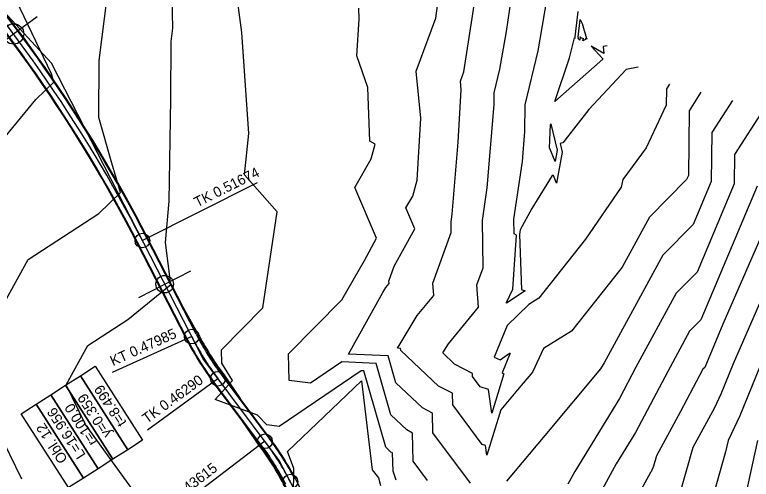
# Model space of a CAD drawing. Extents: x -549394 to -546608, y -1037055 to -1033629.
# Drawn here: x -548001.4 to -547749.6, y -1034578.2 to -1034419.6 of the extents above; entities that cross this region are included whole.
import ezdxf

# ---------------------------------------------------------------- set-up
doc = ezdxf.new("R2010")
doc.units = 0
for name, color, linetype in [('hlavni_vrst', 7, 'Continuous'), ('norm_vrst', 7, 'Continuous'), ('POLYGONY_SITUACE_PO', 7, 'Continuous'), ('u_sirka_1_0m', 7, 'Continuous'), ('u_sirka_1_5m', 7, 'Continuous'), ('x_navrh_C21', 7, 'Continuous'), ('x_osa_C21', 7, 'Continuous'), ('x_popis_oblouky_C21', 7, 'Continuous'), ('x_popis_pricne_rezy_C21', 7, 'Continuous'), ('x_popis_velky_C21', 7, 'Continuous')]:
    doc.layers.add(name, color=color, linetype=linetype)

msp = doc.modelspace()

# ---------------------------------------------------------------- linework, layer by layer
at = {"layer": 'hlavni_vrst'}
for p, q in [((-547972.53, -1034435.18), (-547967.9, -1034398.42)), ((-547847.85, -1034439), (-547844.03, -1034413.98)), ((-547808.1, -1034427.23), (-547808.09, -1034427.11)), ((-547808.1, -1034427.23), (-547808.1, -1034427.23)), ((-547808.09, -1034427.23), (-547808.1, -1034427.23)), ((-547808.09, -1034427.11), (-547808.03, -1034427.23)), ((-547808.03, -1034427.23), (-547808.09, -1034427.23)), ((-547972.63, -1034454.59), (-547972.53, -1034435.18)), ((-547849.06, -1034442.26), (-547847.85, -1034439)), ((-547848.77, -1034445.16), (-547849.06, -1034442.26)), ((-547849.84, -1034463.05), (-547848.77, -1034445.16)), ((-547766.85, -1034446.01), (-547770.88, -1034452.32)), ((-547770.88, -1034452.32), (-547771.13, -1034474.49)), ((-547968.22, -1034470.29), (-547972.63, -1034454.59)), ((-547851.85, -1034487.64), (-547849.84, -1034463.05)), ((-547965.24, -1034480.24), (-547968.22, -1034470.29)), ((-547771.13, -1034474.49), (-547771.77, -1034475.85)), ((-547771.77, -1034475.85), (-547784.47, -1034488.72)), ((-547972.63, -1034487.41), (-547965.24, -1034480.24)), ((-547996.78, -1034503.15), (-547972.63, -1034487.41)), ((-547852.24, -1034490.22), (-547851.85, -1034487.64)), ((-547784.47, -1034488.72), (-547793.79, -1034505.78)), ((-547852.18, -1034493.94), (-547852.24, -1034490.22)), ((-547858.43, -1034511.17), (-547852.18, -1034493.94)), ((-547737, -1034495.44), (-547755.79, -1034538.71)), ((-548017.39, -1034540.43), (-547996.78, -1034503.15)), ((-547793.79, -1034505.78), (-547811.09, -1034527.65)), ((-547858.15, -1034515.37), (-547858.43, -1034511.17)), ((-547863.82, -1034522.3), (-547858.15, -1034515.37)), ((-547869.69, -1034531.9), (-547863.82, -1034522.3)), ((-547811.09, -1034527.65), (-547820.62, -1034533.57)), ((-547870.56, -1034533.46), (-547869.69, -1034531.9)), ((-547869.55, -1034533.5), (-547870.56, -1034533.46)), ((-547869.36, -1034534.18), (-547869.55, -1034533.5)), ((-547856.51, -1034546.33), (-547869.36, -1034534.18)), ((-547820.62, -1034533.57), (-547824.44, -1034541.59)), ((-547755.79, -1034538.71), (-547760.02, -1034549.09)), ((-547998.99, -1034578.18), (-548017.39, -1034540.43)), ((-547824.44, -1034541.59), (-547829.52, -1034547.66)), ((-547851.77, -1034548.83), (-547856.51, -1034546.33)), ((-547829.52, -1034547.66), (-547835.23, -1034554.45)), ((-547851.69, -1034552.72), (-547851.77, -1034548.83)), ((-547760.02, -1034549.09), (-547762.25, -1034553.76)), ((-547841.58, -1034566.29), (-547851.69, -1034552.72)), ((-547835.23, -1034554.45), (-547839.96, -1034569.96)), ((-547762.25, -1034553.76), (-547769.61, -1034567.38)), ((-547840.42, -1034566.64), (-547841.58, -1034566.29)), ((-547839.96, -1034569.96), (-547840.42, -1034566.64)), ((-547769.61, -1034567.38), (-547774.62, -1034585.07))]:
    msp.add_line(p, q, dxfattribs=at)
at = {"layer": 'norm_vrst'}
for p, q in [((-547947.33, -1034424.17), (-547947.99, -1034390.61)), ((-547923.78, -1034425.62), (-547927.84, -1034394.89)), ((-547833.31, -1034425.23), (-547831.2, -1034411.45)), ((-547988.82, -1034439.7), (-548000.83, -1034414.53)), ((-547857.49, -1034420.69), (-547856.85, -1034416.52)), ((-547822.51, -1034431.85), (-547819.48, -1034414.43)), ((-547883.65, -1034421.09), (-547883.74, -1034417.3)), ((-547809.86, -1034427.06), (-547808.83, -1034418.48)), ((-547884.5, -1034433.57), (-547883.65, -1034421.09)), ((-547864.21, -1034438.77), (-547857.49, -1034420.69)), ((-547808.76, -1034427.19), (-547808.14, -1034421.14)), ((-547808.14, -1034421.14), (-547807.38, -1034422.59)), ((-547947.9, -1034428.68), (-547947.33, -1034424.17)), ((-547807.38, -1034422.59), (-547805.94, -1034427.64)), ((-547921.36, -1034460.11), (-547923.78, -1034425.62)), ((-547835.56, -1034438.13), (-547833.31, -1034425.23)), ((-547948, -1034448.39), (-547947.9, -1034428.68)), ((-547811.74, -1034434.26), (-547810.11, -1034427.46)), ((-547810.11, -1034427.46), (-547809.86, -1034427.5)), ((-547809.86, -1034427.5), (-547809.86, -1034427.06)), ((-547808.78, -1034427.51), (-547808.73, -1034427.2)), ((-547808.19, -1034428.24), (-547808.78, -1034427.51)), ((-547808.73, -1034427.2), (-547808.76, -1034427.19)), ((-547808.08, -1034427.33), (-547808.19, -1034428.24)), ((-547808.07, -1034427.33), (-547808.08, -1034427.33)), ((-547807.96, -1034427.34), (-547808.07, -1034427.33)), ((-547807.96, -1034427.34), (-547807.01, -1034427.61)), ((-547807.21, -1034428.43), (-547807, -1034427.63)), ((-547806.3, -1034427.96), (-547807.21, -1034428.43)), ((-547807.21, -1034428.43), (-547807.21, -1034428.43)), ((-547807.21, -1034428.43), (-547807.21, -1034428.43)), ((-547807.21, -1034428.43), (-547807.21, -1034428.43)), ((-547807.02, -1034427.63), (-547807.01, -1034427.61)), ((-547807, -1034427.63), (-547807.02, -1034427.63)), ((-547806.25, -1034427.66), (-547806.3, -1034427.96)), ((-547805.75, -1034427.74), (-547806.25, -1034427.66)), ((-547805.94, -1034427.64), (-547805.75, -1034427.74)), ((-547826.93, -1034450.37), (-547822.51, -1034431.85)), ((-547800.03, -1034432.81), (-547804.32, -1034430.28)), ((-547804.32, -1034430.28), (-547800.3, -1034434.75)), ((-547798.93, -1034430.17), (-547800.25, -1034430.4)), ((-547800.25, -1034430.4), (-547800.03, -1034432.81)), ((-547880.67, -1034444.43), (-547884.5, -1034433.57)), ((-547816.76, -1034449.19), (-547811.74, -1034434.26)), ((-547800.42, -1034434.72), (-547816.76, -1034449.19)), ((-547800.3, -1034434.75), (-547800.42, -1034434.72)), ((-547862.59, -1034454.86), (-547864.21, -1034438.77)), ((-547837.49, -1034446.25), (-547835.56, -1034438.13)), ((-547792.45, -1034438.21), (-547805.11, -1034451.9)), ((-547788.31, -1034437.48), (-547792.45, -1034438.21)), ((-547987.96, -1034442.56), (-547988.82, -1034439.7)), ((-547994.11, -1034448.52), (-547987.96, -1034442.56)), ((-547880.02, -1034462.74), (-547880.67, -1034444.43)), ((-547777.63, -1034443.25), (-547778.66, -1034444.85)), ((-547837.54, -1034450.22), (-547837.49, -1034446.25)), ((-547778.66, -1034444.85), (-547778.72, -1034450.47)), ((-548016.54, -1034475.52), (-547994.11, -1034448.52)), ((-547948.63, -1034483.2), (-547948, -1034448.39)), ((-547756.07, -1034448.78), (-547763.11, -1034459.78)), ((-547839.86, -1034478.64), (-547837.54, -1034450.22)), ((-547827.04, -1034459.45), (-547826.93, -1034450.37)), ((-547805.11, -1034451.9), (-547814.02, -1034463.33)), ((-547778.72, -1034450.47), (-547785.61, -1034465)), ((-547745.28, -1034451.54), (-547755.34, -1034467.25)), ((-547863.86, -1034475.99), (-547862.59, -1034454.86)), ((-547818.6, -1034465.16), (-547818.24, -1034457.04)), ((-547818.24, -1034457.04), (-547818.13, -1034456.86)), ((-547818.13, -1034456.86), (-547815.98, -1034465.84)), ((-547827.87, -1034469.65), (-547827.04, -1034459.45)), ((-547922.84, -1034474.19), (-547921.36, -1034460.11)), ((-547763.11, -1034459.78), (-547763.3, -1034476.45)), ((-547878.16, -1034463.79), (-547880.02, -1034462.74)), ((-547879.53, -1034468.75), (-547878.16, -1034463.79)), ((-547814.02, -1034463.33), (-547814.98, -1034463.51)), ((-547814.98, -1034463.51), (-547814.27, -1034466.48)), ((-547818.44, -1034465.23), (-547818.6, -1034465.16)), ((-547816.67, -1034469.63), (-547818.44, -1034465.23)), ((-547815.98, -1034465.84), (-547816.67, -1034469.63)), ((-547814.27, -1034466.48), (-547816.18, -1034477.05)), ((-547785.61, -1034465), (-547793.51, -1034475.83)), ((-547885.15, -1034478.58), (-547879.53, -1034468.75)), ((-547830.81, -1034489.4), (-547827.87, -1034469.65)), ((-547755.34, -1034467.25), (-547755.45, -1034477.25)), ((-547911.7, -1034486.8), (-547922.84, -1034474.19)), ((-547817.67, -1034474.42), (-547824.67, -1034485.71)), ((-547817.23, -1034474.44), (-547817.67, -1034474.42)), ((-547816.18, -1034477.05), (-547817.23, -1034474.44)), ((-547865.36, -1034481.45), (-547863.86, -1034475.99)), ((-547793.51, -1034475.83), (-547794.08, -1034478.48)), ((-547763.3, -1034476.45), (-547769.49, -1034491.15)), ((-547877.68, -1034495.9), (-547885.15, -1034478.58)), ((-547841.52, -1034489.81), (-547839.86, -1034478.64)), ((-547794.08, -1034478.48), (-547806.3, -1034496.24)), ((-547755.45, -1034477.25), (-547768.17, -1034507.42)), ((-547747.6, -1034478.05), (-547766.85, -1034523.7)), ((-547867.68, -1034485.5), (-547865.36, -1034481.45)), ((-547949.87, -1034497.33), (-547948.63, -1034483.2)), ((-547741.45, -1034484.11), (-547759.32, -1034525.27)), ((-547916.59, -1034519.69), (-547911.7, -1034486.8)), ((-547864.6, -1034492.63), (-547867.68, -1034485.5)), ((-547824.67, -1034485.71), (-547828.59, -1034493.03)), ((-547841.26, -1034505.95), (-547841.52, -1034489.81)), ((-547830.73, -1034494.39), (-547830.81, -1034489.4)), ((-547769.49, -1034491.15), (-547779.89, -1034501.69)), ((-547871.63, -1034505.46), (-547864.6, -1034492.63)), ((-547831.08, -1034513.25), (-547829.91, -1034494.8)), ((-547829.91, -1034494.8), (-547830.73, -1034494.39)), ((-547828.59, -1034493.03), (-547828.82, -1034494.6)), ((-547828.82, -1034494.6), (-547828.15, -1034513.4)), ((-547948.03, -1034511.62), (-547949.87, -1034497.33)), ((-547881.8, -1034503.43), (-547877.68, -1034495.9)), ((-547806.3, -1034496.24), (-547822.23, -1034516.38)), ((-547779.89, -1034501.69), (-547799.97, -1034538.43)), ((-547889.61, -1034516.88), (-547881.8, -1034503.43)), ((-547873.48, -1034510.57), (-547871.63, -1034505.46)), ((-547843.38, -1034511.76), (-547841.26, -1034505.95)), ((-547768.17, -1034507.42), (-547775.31, -1034514.66)), ((-547962.73, -1034523.65), (-547948.03, -1034511.62)), ((-547874.49, -1034512.65), (-547873.43, -1034511.35)), ((-547873.43, -1034511.35), (-547873.48, -1034510.57)), ((-547842.87, -1034519.39), (-547843.38, -1034511.76)), ((-547887.28, -1034535.44), (-547875.58, -1034514.45)), ((-547875.58, -1034514.45), (-547874.49, -1034512.65)), ((-547833.32, -1034517.85), (-547831.08, -1034513.25)), ((-547826.92, -1034513.81), (-547833.24, -1034518.02)), ((-547828.15, -1034513.4), (-547827.94, -1034513.44)), ((-547827.94, -1034513.44), (-547826.92, -1034513.81)), ((-547775.31, -1034514.66), (-547789.09, -1034539.88)), ((-547907.82, -1034535.35), (-547889.61, -1034516.88)), ((-547822.23, -1034516.38), (-547825.69, -1034518.53)), ((-547930.71, -1034534.01), (-547916.59, -1034519.69)), ((-547853.16, -1034531.96), (-547842.87, -1034519.39)), ((-547833.24, -1034518.02), (-547833.32, -1034517.85)), ((-547825.69, -1034518.53), (-547833.1, -1034525.66)), ((-547976.34, -1034532.53), (-547962.73, -1034523.65)), ((-547766.85, -1034523.7), (-547770.72, -1034527.63)), ((-547833.1, -1034525.66), (-547837.5, -1034536.52)), ((-547759.32, -1034525.27), (-547765.52, -1034539.97)), ((-547770.72, -1034527.63), (-547778.21, -1034541.33)), ((-547983.74, -1034545.91), (-547976.34, -1034532.53)), ((-547855.05, -1034535.06), (-547853.16, -1034531.96)), ((-547930.56, -1034538.48), (-547930.71, -1034534.01)), ((-547851.07, -1034538.82), (-547855.05, -1034535.06)), ((-547835.43, -1034537.34), (-547832.26, -1034535.12)), ((-547832.26, -1034535.12), (-547832.01, -1034535.15)), ((-547744.08, -1034533.33), (-547753.53, -1034556.54)), ((-547907.52, -1034544.41), (-547907.82, -1034535.35)), ((-547873.71, -1034536.06), (-547887.28, -1034535.44)), ((-547871.09, -1034545.2), (-547873.71, -1034536.06)), ((-547837.5, -1034536.52), (-547835.43, -1034537.34)), ((-547832.01, -1034535.15), (-547834.81, -1034541.78)), ((-547926.95, -1034544.4), (-547930.56, -1034538.48)), ((-547889.56, -1034538.08), (-547900.27, -1034545.37)), ((-547877.87, -1034538.61), (-547889.56, -1034538.08)), ((-547872.82, -1034556.23), (-547877.87, -1034538.61)), ((-547844.95, -1034542.03), (-547851.07, -1034538.82)), ((-547800.23, -1034538.94), (-547801.2, -1034540.52)), ((-547799.97, -1034538.43), (-547800.23, -1034538.94)), ((-547789.09, -1034539.88), (-547794.73, -1034550.56)), ((-547765.52, -1034539.97), (-547766.14, -1034540.6)), ((-547883, -1034541.13), (-547910.99, -1034560.18)), ((-547882.04, -1034541.17), (-547883, -1034541.13)), ((-547874.54, -1034567.25), (-547882.04, -1034541.17)), ((-547844.93, -1034543.06), (-547844.95, -1034542.03)), ((-547834.16, -1034542.14), (-547838.28, -1034555.65)), ((-547836.61, -1034541.34), (-547836.61, -1034541.34)), ((-547836.61, -1034541.34), (-547836.61, -1034541.34)), ((-547836.61, -1034541.34), (-547836.61, -1034541.34)), ((-547836.61, -1034541.34), (-547836.61, -1034541.34)), ((-547836.61, -1034541.34), (-547836.61, -1034541.34)), ((-547836.61, -1034541.34), (-547836.61, -1034541.34)), ((-547834.81, -1034541.78), (-547834.16, -1034542.14)), ((-547801.2, -1034540.52), (-547820.19, -1034563.23)), ((-547778.21, -1034541.33), (-547789.22, -1034562.18)), ((-547766.14, -1034540.6), (-547767.34, -1034542.78)), ((-547932.87, -1034550.93), (-547926.95, -1034544.4)), ((-547908.1, -1034568.67), (-547882.84, -1034544.56)), ((-547900.27, -1034545.37), (-547907.52, -1034544.41)), ((-547882.84, -1034544.56), (-547879.18, -1034574.92)), ((-547842.26, -1034546.66), (-547844.93, -1034543.06)), ((-547767.34, -1034542.78), (-547773.83, -1034555.08)), ((-547977.13, -1034559.46), (-547983.74, -1034545.91)), ((-547861.95, -1034553.84), (-547871.09, -1034545.2)), ((-547839.41, -1034547.5), (-547842.26, -1034546.66)), ((-547838.28, -1034555.65), (-547839.41, -1034547.5)), ((-547918.39, -1034556.28), (-547932.87, -1034550.93)), ((-547794.73, -1034550.56), (-547809.98, -1034575.52)), ((-547858.58, -1034555.62), (-547861.95, -1034553.84)), ((-547773.83, -1034555.08), (-547781.99, -1034570.2)), ((-547915.22, -1034559.62), (-547918.39, -1034556.28)), ((-547867.39, -1034561.35), (-547872.82, -1034556.23)), ((-547858.44, -1034562.37), (-547858.58, -1034555.62)), ((-547753.53, -1034556.54), (-547757.57, -1034564.98)), ((-547939.34, -1034611.82), (-547977.13, -1034559.46)), ((-547910.99, -1034560.18), (-547915.22, -1034559.62)), ((-547865.39, -1034562.41), (-547867.39, -1034561.35)), ((-547865.2, -1034572.02), (-547865.39, -1034562.41)), ((-547845.65, -1034579.54), (-547858.44, -1034562.37)), ((-547789.22, -1034562.18), (-547795.76, -1034572.88)), ((-547820.19, -1034563.23), (-547833.27, -1034578.79)), ((-547757.57, -1034564.98), (-547758.41, -1034568.77)), ((-547747.51, -1034564.96), (-547753.98, -1034594)), ((-547872.84, -1034568.87), (-547874.54, -1034567.25)), ((-547906.03, -1034574.52), (-547908.1, -1034568.67)), ((-547872.21, -1034569.2), (-547872.84, -1034568.87)), ((-547872.08, -1034575.43), (-547872.21, -1034569.2)), ((-547781.99, -1034570.2), (-547783, -1034573.73)), ((-547758.41, -1034568.77), (-547766.25, -1034596.41)), ((-547860.31, -1034578.59), (-547865.2, -1034572.02)), ((-547795.76, -1034572.88), (-547811.34, -1034601.27)), ((-547906.18, -1034595.2), (-547906.03, -1034574.52)), ((-547879.18, -1034574.92), (-547877.04, -1034577.71)), ((-547783, -1034573.73), (-547783.9, -1034575.65)), ((-547877.04, -1034577.71), (-547876.33, -1034580.33)), ((-547871.01, -1034578.47), (-547872.08, -1034575.43)), ((-547809.98, -1034575.52), (-547812.36, -1034579.85)), ((-547784.03, -1034575.82), (-547810.04, -1034622.26)), ((-547783.9, -1034575.65), (-547784.03, -1034575.82))]:
    msp.add_line(p, q, dxfattribs=at)
at = {"layer": 'POLYGONY_SITUACE_PO'}
for centre in [(-547957.74, -1034496.66), (-547940.89, -1034529.47), (-547931.91, -1034543.83), (-547915.85, -1034565.21), (-547907.16, -1034578.99)]:
    msp.add_circle(centre, 2.5, dxfattribs=at)
at = {"layer": 'u_sirka_1_0m'}
msp.add_circle((-547950.1, -1034511.55), 3, dxfattribs=at)
at = {"layer": 'u_sirka_1_5m'}
msp.add_circle((-548001.76, -1034426.1), 3.5, dxfattribs=at)
at = {"layer": 'x_navrh_C21'}
for p, q in [((-547943.68, -1034519.66), (-547955.97, -1034495.74)), ((-547942.67, -1034530.38), (-547959.52, -1034497.57)), ((-547938.96, -1034528.46), (-547943.91, -1034519.76)), ((-547938.74, -1034528.35), (-547943.69, -1034519.64)), ((-547930.16, -1034542.52), (-547924.49, -1034550.79)), ((-547929.95, -1034542.38), (-547924.29, -1034550.64)), ((-547923.45, -1034558.41), (-547933.5, -1034545.03)), ((-547914.25, -1034564.01), (-547924.3, -1034550.63)), ((-547917.8, -1034566.66), (-547923.47, -1034558.39)), ((-547917.6, -1034566.51), (-547923.26, -1034558.25)), ((-547902.44, -1034583.71), (-547905.39, -1034578.06))]:
    msp.add_line(p, q, dxfattribs=at)
for centre, radius, start, end in [((-548402.5, -1034725.11), 502, 27.187, 42.6945), ((-548402.5, -1034725.11), 498, 27.187, 42.6945), ((-547851.94, -1034483.78), 97.82, 207.1807, 216.9086), ((-547851.94, -1034483.78), 97.57, 207.1775, 216.9117), ((-547851.94, -1034483.78), 102, 207.187, 216.9023), ((-547995.81, -1034625.26), 102, 27.5618, 36.9023), ((-547995.81, -1034625.26), 97.57, 25.4144, 36.9117), ((-547995.81, -1034625.26), 97.82, 25.4026, 36.9086)]:
    msp.add_arc(centre, radius, start, end, dxfattribs=at)
at = {"layer": 'x_osa_C21'}
for points in [[(-547988.85, -1034436.1), (-548081.2, -1034336.01), (-548179.05, -1034250.71), (-548179.05, -1034250.71), (-548370.93, -1034073.7), (-548415.61, -1034028.48), (-548434.5, -1034013.39)], [(-547885.56, -1034620.38), (-547910.94, -1034571.74), (-547937.01, -1034537.03), (-547988.85, -1034436.1)]]:
    msp.add_lwpolyline(points, dxfattribs=at)
for centre, radius, start, end in [((-548402.5, -1034725.11), 500, 27.187, 42.6945), ((-547851.94, -1034483.78), 100, 207.187, 216.9023), ((-547995.81, -1034625.26), 100, 27.5618, 36.9023)]:
    msp.add_arc(centre, radius, start, end, dxfattribs=at)
at = {"layer": 'x_popis_oblouky_C21'}
for points in [[(-547918.46, -1034476.95), (-547957.74, -1034496.66)], [(-547940.89, -1034529.47), (-547968.07, -1034541.68)], [(-547931.91, -1034543.83), (-547955.99, -1034561.37)], [(-547915.85, -1034565.21), (-547950.8, -1034591.86)]]:
    msp.add_lwpolyline(points, dxfattribs=at)
for points in [[(-547962.74, -1034568.08), (-547978.94, -1034542.83), (-547973.89, -1034539.59), (-547957.69, -1034564.84)], [(-547967.79, -1034571.32), (-547983.99, -1034546.07), (-547978.94, -1034542.83), (-547962.74, -1034568.08)], [(-547972.84, -1034574.56), (-547989.04, -1034549.31), (-547983.99, -1034546.07), (-547967.79, -1034571.32)], [(-547977.89, -1034577.8), (-547994.09, -1034552.55), (-547989.04, -1034549.31), (-547972.84, -1034574.56)], [(-547982.94, -1034581.04), (-547999.14, -1034555.8), (-547994.09, -1034552.55), (-547977.89, -1034577.8)]]:
    msp.add_lwpolyline(points, close=True, dxfattribs=at)
at = {"layer": 'x_popis_pricne_rezy_C21'}
for points in [[(-548009.78, -1034432.08), (-548001.76, -1034426.1), (-547993.75, -1034420.12)], [(-547958.99, -1034516.12), (-547950.1, -1034511.55), (-547941.2, -1034506.98)]]:
    msp.add_lwpolyline(points, dxfattribs=at)
at = {"layer": 'x_popis_velky_C21'}
for p, q in [((-547939.33, -1034528.67), (-547956.19, -1034495.86)), ((-547942.45, -1034530.27), (-547959.3, -1034497.46)), ((-547917.25, -1034566.26), (-547933.3, -1034544.88)), ((-547914.45, -1034564.16), (-547930.51, -1034542.77))]:
    msp.add_line(p, q, dxfattribs=at)
for centre, radius, start, end in [((-548402.5, -1034725.11), 501.75, 27.187, 42.6945), ((-548402.5, -1034725.11), 498.25, 27.187, 42.6945), ((-547851.94, -1034483.78), 98.25, 207.187, 216.9023), ((-547851.94, -1034483.78), 101.75, 207.187, 216.9023), ((-547995.81, -1034625.26), 101.75, 27.5618, 36.9023), ((-547995.81, -1034625.26), 98.25, 27.5618, 36.9023)]:
    msp.add_arc(centre, radius, start, end, dxfattribs=at)

# ---------------------------------------------------------------- texts
at = {"layer": 'x_popis_oblouky_C21'}
for s, rotation, p in [('TK 0.51674', 26.642, (-547938.98, -1034485.39)), ('KT 0.47985', 24.1934, (-547967.8, -1034539.6)), ('TK 0.46290', 36.0839, (-547956.17, -1034559.31)), ('t=8.499', 122.7069, (-547963, -1034558.8)), ('y=0.359', 122.7069, (-547968.1, -1034562.62)), ('r=100.0', 122.7069, (-547972.97, -1034565.33)), ('L=16.956', 122.7069, (-547976.99, -1034569.85)), ('Obl. 12', 122.7069, (-547983.14, -1034571.37)), ('KT 0.43615', 37.3171, (-547951.02, -1034589.69))]:
    msp.add_text(s, height=3.5, rotation=rotation, dxfattribs=at).set_placement(p)

doc.saveas('drawing.dxf')
